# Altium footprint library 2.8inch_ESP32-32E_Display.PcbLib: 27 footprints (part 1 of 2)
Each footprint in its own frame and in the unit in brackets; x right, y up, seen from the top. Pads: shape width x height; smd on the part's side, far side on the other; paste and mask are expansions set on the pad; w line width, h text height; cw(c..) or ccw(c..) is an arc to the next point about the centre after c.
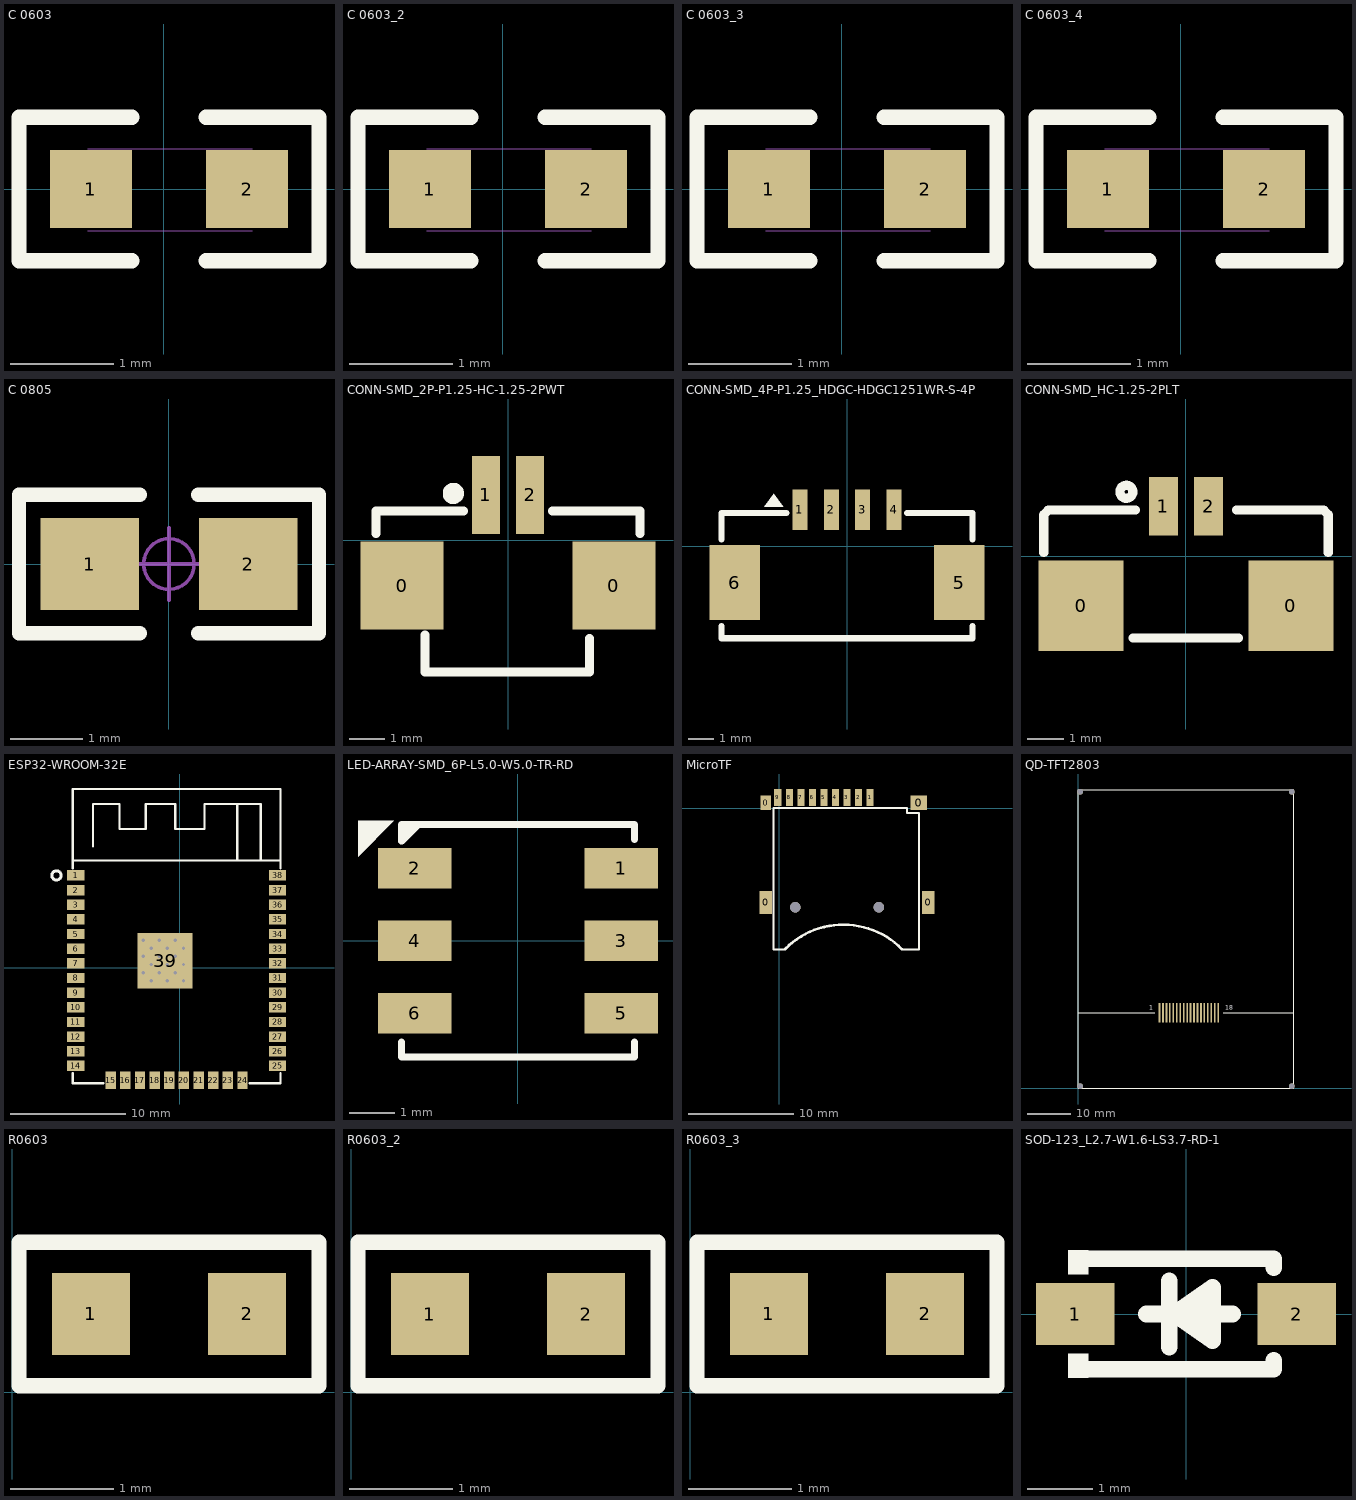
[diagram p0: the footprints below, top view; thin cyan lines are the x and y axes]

## C 0603 [mm] "无极性贴片电容"
pads (2):
  rect 0.8x0.76 smd: 1(-0.711,0) 2(0.809,0)
Top Overlay:
  lines w0.15: -0.311,-0.7 -1.411,-0.7 -1.411,0.7 -0.311,0.7 ; 0.409,-0.7 1.509,-0.7 1.509,0.7 0.409,0.7
Mechanical 13:
  lines w0.01: -0.742,-0.406 0.858,-0.406 ; -0.742,0.394 0.858,0.394
3D body "C 0603.STEP": height 0.81, standoff -0.01, extent -0.742,-0.41 0.858,0.41

## C 0603_2 [mm]
pads (2):
  rect 0.8x0.76 smd: 1(-0.711,0) 2(0.809,0)
Top Overlay:
  lines w0.15: -0.311,-0.7 -1.411,-0.7 -1.411,0.7 -0.311,0.7 ; 0.409,-0.7 1.509,-0.7 1.509,0.7 0.409,0.7
Mechanical 13:
  lines w0.01: -0.742,-0.406 0.858,-0.406 ; -0.742,0.394 0.858,0.394
3D body "C 0603.STEP": height 0.81, standoff -0.01, extent -0.742,-0.41 0.858,0.41

## C 0603_3 [mm]
pads (2):
  rect 0.8x0.76 smd: 1(-0.711,0) 2(0.809,0)
Top Overlay:
  lines w0.15: -0.311,-0.7 -1.411,-0.7 -1.411,0.7 -0.311,0.7 ; 0.409,-0.7 1.509,-0.7 1.509,0.7 0.409,0.7
Mechanical 13:
  lines w0.01: -0.742,-0.406 0.858,-0.406 ; -0.742,0.394 0.858,0.394
3D body "C 0603.STEP": height 0.81, standoff -0.01, extent -0.742,-0.41 0.858,0.41

## C 0603_4 [mm]
pads (2):
  rect 0.8x0.76 smd: 1(-0.711,0) 2(0.809,0)
Top Overlay:
  lines w0.15: -0.311,-0.7 -1.411,-0.7 -1.411,0.7 -0.311,0.7 ; 0.409,-0.7 1.509,-0.7 1.509,0.7 0.409,0.7
Mechanical 13:
  lines w0.01: -0.742,-0.406 0.858,-0.406 ; -0.742,0.394 0.858,0.394
3D body "C 0603.STEP": height 0.81, standoff -0.01, extent -0.742,-0.41 0.858,0.41

## C 0805 [mm] "无极性贴片电容"
height 0.5
pads (2):
  rect 1.36x1.27 smd: 1(-1.094,0) 2(1.094,0)
Top Overlay:
  lines w0.2: -0.406,-0.955 -2.074,-0.955 -2.074,0.955 -0.406,0.955 ; 0.406,-0.955 2.074,-0.955 ; 0.406,0.955 2.074,0.955 ; 2.075,-0.955 2.075,0.955
Mechanical 15:
  circle w0.05: c0,0 r0.35
  lines w0.05: -0.5,0 0.5,0 ; 0,-0.5 0,0.5
3D body "C 0805.STEP": height 0.51, standoff -0.01, extent -1,-0.61 1,0.61

## CONN-SMD_2P-P1.25-HC-1.25-2PWT [mm]
pads (4):
  rect 2.35x2.5 smd paste+0 mask+0.05: 0(-3.005,-1.285) 0(3.005,-1.285)
  rect 0.8x2.2 smd paste+0 mask+0.05: 1(-0.625,1.285) 2(0.625,1.285)
Top Overlay:
  circle w0.3: c-1.55,1.33 r0.15
  lines w0.254: -3.75,0.196 -3.75,0.835 -1.256,0.835 ; -2.36,-2.69 -2.36,-3.73 2.31,-3.73 2.31,-2.78 ; 1.256,0.835 3.75,0.835 3.75,0.196

## CONN-SMD_4P-P1.25_HDGC-HDGC1251WR-S-4P [mm]
pads (6):
  rect 0.6x1.6 smd mask+0.05: 1(-1.875,1.45) 2(-0.625,1.45) 3(0.625,1.45) 4(1.875,1.45)
  rect 2x3 smd mask+0.05: 5(4.475,-1.45) 6(-4.475,-1.45)
Top Overlay:
  region: -3.175,1.577 -3.302,1.577 -2.921,2.085 -2.54,1.577 -3.175,1.577
  lines w0.254: -5,-3.181 -5,-3.669 5,-3.669 5,-3.181 ; -5,0.281 -5,1.323 -2.413,1.323 ; 2.406,1.323 5,1.323 5,0.281

## CONN-SMD_HC-1.25-2PLT [mm]
pads (4):
  rect 2.35x2.5 smd paste+0 mask+0.05: 0(-2.9,-1.38) 0(2.9,-1.38)
  rect 0.8x1.62 smd paste+0 mask+0.05: 1(-0.625,1.38) 2(0.625,1.38)
Top Overlay:
  circle w0.254: c-1.651,1.778 r0.18
  lines w0.254: -3.937,0.101 -3.937,1.143 -3.81,1.27 -1.397,1.27 ; -1.47,-2.27 1.451,-2.27 ; 1.397,1.27 3.81,1.27 3.937,1.143 3.937,0.101

## ESP32-WROOM-32E [mm]
pads (39):
  rect 1.5x0.9 smd mask+0.051: 1(-9.004,7.987) 2(-9.004,6.717) 3(-9.004,5.447) 4(-9.004,4.177) 5(-9.004,2.907) 6(-9.004,1.637) 7(-9.004,0.367) 8(-9.004,-0.903) 9(-9.004,-2.173) 10(-9.004,-3.443) 11(-9.004,-4.713) 12(-9.004,-5.983) 13(-9.004,-7.253) 14(-9.004,-8.523) 25(8.496,-8.523) 26(8.496,-7.253) 27(8.496,-5.983) 28(8.496,-4.713) 29(8.496,-3.443) 30(8.496,-2.173) 31(8.496,-0.903) 32(8.496,0.367) 33(8.496,1.637) 34(8.496,2.907) 35(8.496,4.177) 36(8.496,5.447) 37(8.496,6.717) 38(8.496,7.987)
  rect 0.9x1.5 smd mask+0.051: 15(-5.969,-9.774) 16(-4.699,-9.774) 17(-3.429,-9.774) 18(-2.159,-9.774) 19(-0.889,-9.774) 20(0.381,-9.774) 21(1.651,-9.774) 22(2.921,-9.774) 23(4.191,-9.774) 24(5.461,-9.774)
  rect 4.8x4.8 smd mask+0.051: 39(-1.254,0.576)
via -1.054,-1.133 diameter 0.5 hole 0.3
via -2.454,-1.133 diameter 0.5 hole 0.3
via -2.454,0.267 diameter 0.5 hole 0.3
via -1.054,0.267 diameter 0.5 hole 0.3
via -1.054,1.667 diameter 0.5 hole 0.3
via -0.354,0.967 diameter 0.5 hole 0.3
via -0.354,-0.433 diameter 0.5 hole 0.3
via -3.154,-0.433 diameter 0.5 hole 0.3
via -3.154,0.967 diameter 0.5 hole 0.3
via -2.454,1.667 diameter 0.5 hole 0.3
via -1.754,-0.433 diameter 0.5 hole 0.3
via -1.754,0.967 diameter 0.5 hole 0.3
via -1.754,2.367 diameter 0.5 hole 0.3
via -0.354,2.367 diameter 0.5 hole 0.3
via 0.346,1.667 diameter 0.5 hole 0.3
via 0.346,0.267 diameter 0.5 hole 0.3
via -3.154,2.367 diameter 0.5 hole 0.3
via 0.346,-1.133 diameter 0.5 hole 0.3
Top Overlay:
  circle w0.254: c-10.668,7.986 r0.402
  lines w0.203: -9.254,-9.15 -9.254,-10.023 -6.596,-10.023 ; -9.254,8.613 -9.254,15.476 8.746,15.477 8.746,8.614 ; -9.254,9.287 8.746,9.287 ; -7.493,10.489 -7.493,14.172 -5.207,14.172 -5.207,12.013 -2.921,12.013 -2.921,14.172 -0.381,14.172 -0.381,12.013 2.159,12.013 2.159,14.172 5.011,14.172 5.011,9.287 ; 4.808,14.172 7.043,14.172 7.043,9.287 ; 6.088,-10.023 8.746,-10.023 8.746,-9.15
3D body "ESP32-WROOM-32E_20210903.STEP": height 3.2, standoff 0.1, extent -9.254,-10.023 8.746,15.477

## LED-ARRAY-SMD_6P-L5.0-W5.0-TR-RD [mm]
pads (6):
  rect 1.625x0.896 smd mask+0.051: 1(2.288,1.6) 2(-2.288,1.6) 3(2.288,0) 4(-2.288,0) 5(2.288,-1.6) 6(-2.288,-1.6)
Top Overlay:
  region: -2.874,2.652 -3.54,2.652 -3.54,1.859 -2.747,2.652
  region: -2.54,2.159 -2.54,2.202 -2.576,2.239
  region: -2.286,2.576 -2.576,2.576 -2.576,2.239 -2.497,2.239 -2.159,2.576
  lines w0.152: -2.576,-2.239 -2.576,-2.576 2.576,-2.576 2.576,-2.239 ; -2.202,2.576 -2.576,2.202 -2.576,2.576 2.576,2.576 2.576,2.239

## MicroTF [mm]
height 2.65
pads (15):
  rect 1x1.4 smd: 0(-1.3,0.526)
  rect 1.2x2.2 smd: 0(-1.3,-8.994) 0(14.2,-8.994)
  rect 1.6x1.4 smd: 0(13.3,0.526)
  rect 0.7x1.6 smd: 1(8.65,1.026) 2(7.55,1.026) 3(6.45,1.026) 4(5.35,1.026) 5(4.25,1.026) 6(3.15,1.026) 7(2.05,1.026) 8(0.95,1.026) 9(-0.15,1.026)
  round 1 hole 1 unplated: ""(1.52,-9.474) ""(9.5,-9.474)
Top Overlay:
  lines w0.2: 0.563,-13.5 -0.559,-13.5 -0.559,0.026 12.192,0.026 ; 11.709,-13.5 13.335,-13.5 13.335,-0.483
  lines w0.203: 12.192,0.026 12.192,-0.483 13.335,-0.483
  lines w0.254: 0.563,-13.43 cw(c6.113,-18.98) 11.721,-13.489
3D body "User Library-MEM2055-00-190-01-A_revG.STEP": height 1.85, standoff -0.6, extent -1.548,-13.472 14.452,1.778

## QD-TFT2803 [mm]
pads (22):
  round 1.3 hole 1.3 unplated: 0(0.47,0.47) 0(0.47,68.73) 0(49.53,0.47) 0(49.53,68.73)
  rect 0.4x4.5 smd: 1(18.86,17.46) 2(19.66,17.46) 3(20.46,17.46) 4(21.26,17.46) 5(22.06,17.46) 6(22.86,17.46) 7(23.66,17.46) 8(24.46,17.46) 9(25.26,17.46) 10(26.06,17.46) 11(26.86,17.46) 12(27.66,17.46) 13(28.46,17.46) 14(29.26,17.46) 15(30.06,17.46) 16(30.86,17.46) 17(31.66,17.46) 18(32.46,17.46)
Top Overlay:
  lines w0.254: 0,17.46 17.7,17.46 ; 33.633,17.46 50,17.46 ; 0,0 0,69.2 50,69.2 50,0 0,0
  text "1" at 16.51,18.161 h1.02
  text "18" at 34.155,18.246 h1.02

## R0603 [mm]
pads (2):
  rect 0.76x0.8 smd: 1(0.766,0.762) 2(2.286,0.762)
Top Overlay:
  lines w0.15: 0.066,0.062 0.066,1.462 2.986,1.462 2.986,0.062 0.066,0.062
3D body "RES0603.STEP": height 0.65, standoff 0.2, extent 0.749,0.348 2.349,1.168

## R0603_2 [mm]
pads (2):
  rect 0.76x0.8 smd: 1(0.766,0.762) 2(2.286,0.762)
Top Overlay:
  lines w0.15: 0.066,0.062 2.986,0.062 2.986,1.462 0.066,1.462 0.066,0.062
3D body "RES0603.STEP": height 0.65, standoff 0.2, extent 0.749,0.348 2.349,1.168

## R0603_3 [mm]
pads (2):
  rect 0.76x0.8 smd: 1(0.766,0.762) 2(2.286,0.762)
Top Overlay:
  lines w0.15: 0.066,0.062 0.066,1.462 2.986,1.462 2.986,0.062 0.066,0.062
3D body "RES0603.STEP": height 0.65, standoff 0.2, extent 0.749,0.348 2.349,1.168

## SOD-123_L2.7-W1.6-LS3.7-RD-1 [mm]
pads (2):
  rect 1.2x0.95 smd: 1(-1.7,0) 2(1.7,0)
Top Overlay:
  region: -1.502,-0.977 -1.502,-0.607 -1.806,-0.607 -1.806,-0.977
  region: -1.502,0.977 -1.502,0.607 -1.806,0.607 -1.806,0.977
  region: 0.406,-0.406 0.406,0.406 -0.178,0
  lines w0.254: -1.644,0.849 -1.643,0.85 -1.346,0.85 1.346,0.85 1.346,0.706 ; -1.639,-0.849 -1.638,-0.85 -1.346,-0.85 1.346,-0.85 1.346,-0.706 ; -0.61,0 -0.28,0 ; -0.254,-0.508 -0.254,0.508 ; 0.406,0 0.72,0 ; -0.178,0 0.406,-0.406 0.406,0.406 -0.178,0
